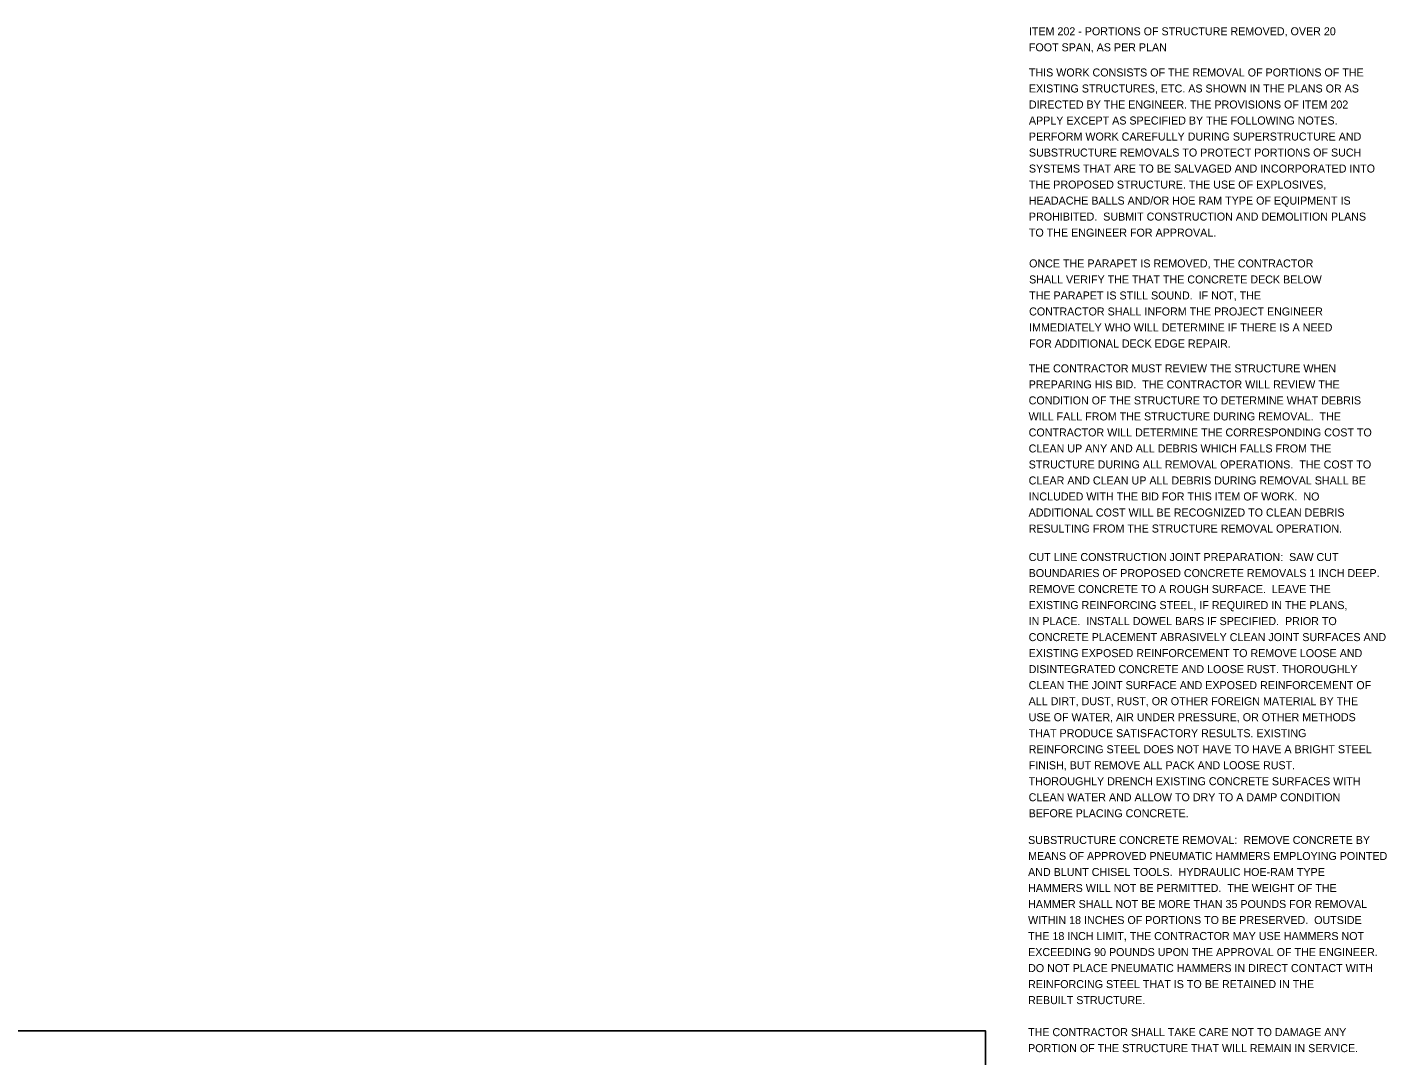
# Model space of a CAD drawing. Extents: x -15 to 144, y -80 to 40.
# Drawn here: x 17.24 to 41.02, y 21.56 to 39.55 of the extents above; entities that cross this region are included whole.
import ezdxf

# ---------------------------------------------------------------- set-up
doc = ezdxf.new("R2010")
doc.units = 0
doc.layers.add('BR_P_Gen_Text', color=7, linetype='Continuous')
doc.layers.add('SH_Cut_Line', color=7, linetype='Continuous')

msp = doc.modelspace()

# ---------------------------------------------------------------- linework, layer by layer
at = {"layer": 'SH_Cut_Line'}
msp.add_lwpolyline([(0, 0), (34, 0), (34, 22), (0, 22)], close=True, dxfattribs=at)

# ---------------------------------------------------------------- texts
at = {"layer": 'BR_P_Gen_Text'}
for s, p in [('ITEM 202 - PORTIONS OF STRUCTURE REMOVED, OVER 20', (34.761, 39.406)), ('FOOT SPAN, AS PER PLAN', (34.761, 39.126)), ('THIS WORK CONSISTS OF THE REMOVAL OF PORTIONS OF THE ', (34.761, 38.686)), ('EXISTING STRUCTURES, ETC. AS SHOWN IN THE PLANS OR AS', (34.761, 38.406)), ('DIRECTED BY THE ENGINEER. THE PROVISIONS OF ITEM 202 ', (34.761, 38.126)), ('APPLY EXCEPT AS SPECIFIED BY THE FOLLOWING NOTES. ', (34.761, 37.846)), ('PERFORM WORK CAREFULLY DURING SUPERSTRUCTURE AND ', (34.761, 37.566)), ('SUBSTRUCTURE REMOVALS TO PROTECT PORTIONS OF SUCH ', (34.761, 37.286)), ('SYSTEMS THAT ARE TO BE SALVAGED AND INCORPORATED INTO ', (34.761, 37.006)), ('THE PROPOSED STRUCTURE. THE USE OF EXPLOSIVES, ', (34.761, 36.726)), ('HEADACHE BALLS AND/OR HOE RAM TYPE OF EQUIPMENT IS ', (34.761, 36.446)), ('PROHIBITED.  SUBMIT CONSTRUCTION AND DEMOLITION PLANS ', (34.761, 36.166)), ('TO THE ENGINEER FOR APPROVAL.', (34.761, 35.886)), ('ONCE THE PARAPET IS REMOVED, THE CONTRACTOR', (34.765, 35.347)), ('SHALL VERIFY THE THAT THE CONCRETE DECK BELOW', (34.765, 35.067)), ('THE PARAPET IS STILL SOUND.  IF NOT, THE ', (34.765, 34.787)), ('CONTRACTOR SHALL INFORM THE PROJECT ENGINEER', (34.765, 34.507)), ('IMMEDIATELY WHO WILL DETERMINE IF THERE IS A NEED', (34.765, 34.227)), ('FOR ADDITIONAL DECK EDGE REPAIR.', (34.765, 33.947)), ('THE CONTRACTOR MUST REVIEW THE STRUCTURE WHEN ', (34.757, 33.512)), ('PREPARING HIS BID.  THE CONTRACTOR WILL REVIEW THE ', (34.757, 33.232)), ('CONDITION OF THE STRUCTURE TO DETERMINE WHAT DEBRIS ', (34.757, 32.952)), ('WILL FALL FROM THE STRUCTURE DURING REMOVAL.  THE ', (34.757, 32.672)), ('CONTRACTOR WILL DETERMINE THE CORRESPONDING COST TO ', (34.757, 32.392)), ('CLEAN UP ANY AND ALL DEBRIS WHICH FALLS FROM THE ', (34.757, 32.112)), ('STRUCTURE DURING ALL REMOVAL OPERATIONS.  THE COST TO ', (34.757, 31.832)), ('CLEAR AND CLEAN UP ALL DEBRIS DURING REMOVAL SHALL BE ', (34.757, 31.552)), ('INCLUDED WITH THE BID FOR THIS ITEM OF WORK.  NO ', (34.757, 31.272)), ('ADDITIONAL COST WILL BE RECOGNIZED TO CLEAN DEBRIS ', (34.757, 30.992)), ('RESULTING FROM THE STRUCTURE REMOVAL OPERATION.', (34.757, 30.712)), ('CUT LINE CONSTRUCTION JOINT PREPARATION:  SAW CUT ', (34.757, 30.213)), ('BOUNDARIES OF PROPOSED CONCRETE REMOVALS 1 INCH DEEP.  ', (34.757, 29.933)), ('REMOVE CONCRETE TO A ROUGH SURFACE.  LEAVE THE ', (34.757, 29.653)), ('EXISTING REINFORCING STEEL, IF REQUIRED IN THE PLANS, ', (34.757, 29.373)), ('IN PLACE.  INSTALL DOWEL BARS IF SPECIFIED.  PRIOR TO ', (34.757, 29.093)), ('CONCRETE PLACEMENT ABRASIVELY CLEAN JOINT SURFACES AND ', (34.757, 28.813)), ('EXISTING EXPOSED REINFORCEMENT TO REMOVE LOOSE AND ', (34.757, 28.533)), ('DISINTEGRATED CONCRETE AND LOOSE RUST. THOROUGHLY ', (34.757, 28.253)), ('CLEAN THE JOINT SURFACE AND EXPOSED REINFORCEMENT OF ', (34.757, 27.973)), ('ALL DIRT, DUST, RUST, OR OTHER FOREIGN MATERIAL BY THE ', (34.757, 27.693)), ('USE OF WATER, AIR UNDER PRESSURE, OR OTHER METHODS ', (34.757, 27.413)), ('THAT PRODUCE SATISFACTORY RESULTS. EXISTING ', (34.757, 27.133)), ('REINFORCING STEEL DOES NOT HAVE TO HAVE A BRIGHT STEEL ', (34.757, 26.853)), ('FINISH, BUT REMOVE ALL PACK AND LOOSE RUST.  ', (34.757, 26.573)), ('THOROUGHLY DRENCH EXISTING CONCRETE SURFACES WITH ', (34.757, 26.293)), ('CLEAN WATER AND ALLOW TO DRY TO A DAMP CONDITION ', (34.757, 26.013)), ('BEFORE PLACING CONCRETE.', (34.757, 25.733)), ('SUBSTRUCTURE CONCRETE REMOVAL:  REMOVE CONCRETE BY ', (34.747, 25.266)), ('MEANS OF APPROVED PNEUMATIC HAMMERS EMPLOYING POINTED ', (34.747, 24.986)), ('AND BLUNT CHISEL TOOLS.  HYDRAULIC HOE-RAM TYPE ', (34.747, 24.706)), ('HAMMERS WILL NOT BE PERMITTED.  THE WEIGHT OF THE ', (34.747, 24.426)), ('HAMMER SHALL NOT BE MORE THAN 35 POUNDS FOR REMOVAL ', (34.747, 24.146)), ('WITHIN 18 INCHES OF PORTIONS TO BE PRESERVED.  OUTSIDE ', (34.747, 23.866)), ('THE 18 INCH LIMIT, THE CONTRACTOR MAY USE HAMMERS NOT ', (34.747, 23.586)), ('EXCEEDING 90 POUNDS UPON THE APPROVAL OF THE ENGINEER. ', (34.747, 23.306)), ('DO NOT PLACE PNEUMATIC HAMMERS IN DIRECT CONTACT WITH ', (34.747, 23.026)), ('REINFORCING STEEL THAT IS TO BE RETAINED IN THE ', (34.747, 22.746)), ('REBUILT STRUCTURE. ', (34.747, 22.466)), ('THE CONTRACTOR SHALL TAKE CARE NOT TO DAMAGE ANY ', (34.747, 21.906)), ('PORTION OF THE STRUCTURE THAT WILL REMAIN IN SERVICE. ', (34.747, 21.626))]:
    msp.add_text(s, height=0.14, dxfattribs=at).set_placement(p)

doc.saveas('drawing.dxf')
